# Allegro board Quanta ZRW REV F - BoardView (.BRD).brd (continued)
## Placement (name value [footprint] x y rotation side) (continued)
D11  *rb500v-40  [DSM]  198.34 40.64 270 top
D12  sdmk0340l-7-f  [DSMV]  200.24 40.64 270 top
D14  *rb500v-40  [DSM]  203.92 40.64 270 top
D15  *rb500v-40  [DSM]  44.16 39.75 180 top
D16  rb500v-40  [DSM]  44.16 37.71 180 top
D17  *rb500v-40  [DSM]  198.44 33.52 270 top
D18  rb500v-40  [DSM]  200.22 33.52 270 top
D19  *rb500v-40  [DSM]  201.99 33.52 270 top
D20  *rb500v-40  [DSM]  203.77 33.52 270 top
D21  az5725-01f  [D-SOD523-1_2X0_8-0_65H]  14.06 21.1 90 top
D22  az5725-01f  [D-SOD523-1_2X0_8-0_65H]  18.76 10.41 0 top
D23  *vport_6  [RC0603]  66.13 8.76 90 top
D24  *5.5v/25v/410p_4  [CC0402]  67.4 7.49 90 top
D25  *5.5v/25v/410p_4  [CC0402]  68.54 7.49 90 top
D26  *5.5v/25v/410p_4  [CC0402]  59.27 7.36 90 top
D27  *5.5v/25v/410p_4  [CC0402]  60.41 7.36 90 top
D28  *vport_6  [RC0603]  63.33 6.73 0 top
D30  rb501v-40  [DSM]  17.11 67.05 180 bottom
D31  rb501v-40  [DSM]  17.11 65.27 180 bottom
D33  *az5125-01h.r7g  [D-SOD523-1_2X0_8-0_65H]  14.06 20.95 90 bottom
D34  *vport_6  [RC0603]  144.74 15.87 90 bottom
D35  gs@rb500v-40  [DSM]  208.24 54.43 90 top
HOLE1  *h-tc315bc354d217p2  [H-TC315BC354D217P2]  229.4 191.7 0 top
HOLE2  *h-tc315bc354d134p2  [H-TC315BC354D134P2]  121.89 177.9 0 top
HOLE3  *h-tc256ic201bc236d161p2  [H-TC256IC201BC236D161P2]  136.52 146.63 0 top
HOLE4  *o-zrta-4  [O-ZRTA-4]  224.89 131.4 0 top
HOLE5  *h-zrw-1  [H-ZRW-1]  10.99 119.9 0 top
HOLE6  *h-tc256ic201bc236d161p2  [H-TC256IC201BC236D161P2]  110.53 101.64 0 top
HOLE7  *h-tc256ic201bc236d161p2  [H-TC256IC201BC236D161P2]  162.5 101.63 0 top
HOLE8  *h-o112x120d112x120n  [H-O112X120D112X120N]  5.29 99.4 90 top
HOLE9  *o-zrta-2  [O-ZRTA-2]  71.89 84.9 0 top
HOLE10  *h-o152x93d152x93n  [H-O152X93D152X93N]  231.15 84.9 0 top
HOLE11  *o-zrta-3  [O-ZRTA-3]  225.4 84.9 0 top
HOLE12  *h-tc315bc354d134p2  [H-TC315BC354D134P2]  17.27 58.62 0 top
HOLE13  *o-zrz-7  [O-ZRZ-7]  186.65 36.2 0 top
HOLE14  *h-o138x114d138x114n  [H-O138X114D138X114N]  217.89 26.3 0 top
HOLE15  *o-zrz-8  [O-ZRZ-8]  185.14 15.65 0 top
HOLE16  *h-c118d118  [H-C118D118]  12.79 5.9 0 top
HOLE17  *o-zrta-5  [O-ZRTA-5]  6.39 5.1 0 top
HOLE18  *h-tc315bc354d134p2  [H-TC315BC354D134P2]  217.89 5.1 0 top
HOLE19  *h-tc315bc354d134p2  [H-TC315BC354D134P2]  74.57 5.1 0 top
HOLE20  ev@mbzrq001010  [H-C236IC180D140P2]  161.21 178.33 180 bottom
HOLE21  ev@mbzrq001010  [H-C236D140P2]  203.42 136.13 180 bottom
HOLE22  h-c236d142p2  [H-C236D142P2]  213.09 99.47 180 bottom
HOLE23  *h-c256d134p2  [H-C256D134P2]  11.34 99.4 0 top
J1  *jump  [JOPEN25X30_S]  81.88 77.72 180 bottom
JDIM1  ddr3-dimm1_h=4.0_rvs  [DDR-DDRRK-20401-TP5B-204P-RUV]  132.89 64.35 180 bottom
JDIM2  ddr3-dimm1_h=4.0_std  [DDR-DDRSK-20401-TP4B-204P-SMT]  132.89 51.15 0 bottom
JP16  gt3@0.001/f_3720  [RC3720-SMT]  54.83 74.04 0 bottom
L1  ev@blm15px330sn1dev_4  [RC0402]  168.62 164.08 270 top
L2  ev@blm15px330sn1d_4  [RC0402]  185.7 142.89 0 top
L3  ev@hcb1005kf-181t15(180,1500ma)  [RC0402]  183.35 142.24 270 top
L4  80ohm@100mhz  [RC0402]  27.14 112.64 0 top
L5  blm18bb470_6  [RC0603]  13.42 108.78 0 top
L6  blm18bb470_6  [RC0603]  13.42 107.52 0 top
L7  blm18bb470_6  [RC0603]  13.42 105.49 0 top
L11  blm15ag121sn1d(120,500ma)_4  [RC0402]  197.4 37.79 0 top
L12  blm15ag121sn1d(120,500ma)_4  [RC0402]  197.4 36.78 0 top
L13  pby160808t-600y-n(60,3a)  [RC0603]  46.06 36.06 0 top
L16  hcb2012kf220t60/6a/22ohm_8  [RC0805]  45.38 31.75 0 top
L18  hcb1608kf-121t30_3a  [RC0603]  40.45 27.43 90 top
L19  *short_6  [SHORT0603]  204.94 24.76 0 top
L20  80ohm@100mhz  [RC0402]  24.85 111.63 90 bottom
L21  80ohm@100mhz  [RC0402]  17.18 106.52 270 bottom
L22  blm15ag121sn1d(120,500ma)_4  [RC0402]  207.73 49.14 270 bottom
LED1  led_amber/blue  [LEDLTST-S326KGJRKT-3P-SMT]  58.92 4.39 0 bottom
LED2  led_amber/blue  [LEDLTST-S326KGJRKT-3P-SMT]  66.89 4.39 0 bottom
MR1  ah9249ntr-g1  [SOT23_123-2_8-1_9]  62.9 2.92 270 top
NOREF  -  [unnamed]  221.22 19.78 0 top
NOREF#2  -  [unnamed]  20.94 118.99 0 top
NOREF#3  -  [#2]  112.1 -37.6 0 top
NOREF#4  -  [#2]  108.55 17.52 0 top
NOREF#5  -  [#2]  64.66 62.94 0 top
NOREF#6  -  [#2]  61.3 -79.76 0 top
NOREF#7  -  [unnamed]  229.83 199.26 0 top
NOREF#8  -  [#2]  119.21 17.78 180 bottom
NOREF#9  -  [#2]  89.57 51.28 180 bottom
NOREF#10  -  [unnamed]  16.7 117.29 180 bottom
NOREF#11  -  [unnamed]  228.05 199.39 180 bottom
NOREF#12  -  [unnamed]  221.75 28.62 180 bottom
PC1  *0.01u/50v_4  [CC0402]  179.57 200.53 0 top
PC2  0.1u/50v_6  [CC0603]  204.43 199.64 180 top
PC3  100p/50v_4  [CC0402]  210.02 199.13 180 top
PC4  *680p/50v_6  [CC0603]  194.4 198.5 180 top
PC5  0.1u/50v_6  [CC0603]  204.3 198.12 0 top
PC6  100p/50v_4  [CC0402]  210.02 197.99 180 top
PC7  *100p/50v_4  [CC0402]  210.02 196.97 180 top
PC8  *47p/50v_4  [CC0402]  158.58 195.96 90 top
PC9  *47p/50v_4  [CC0402]  160.62 195.96 90 top
PC10  0.01u/50v_4  [CC0402]  150.46 192.53 270 top
PC11  *0.01u/50v_4  [CC0402]  151.47 192.53 270 top
PC12  *0.01u/50v_4  [CC0402]  150.96 190.88 0 top
PC13  0.1u/50v_6  [CC0603]  214.97 190.11 180 top
PC14  0.1u/25v_4  [CC0402]  150.46 189.23 270 top
PC15  1000p/50v_4  [CC0402]  151.47 189.23 270 top
PC16  330p/25v_4  [CC0402]  152.49 189.23 270 top
PC17  0.022u/25v_4  [CC0402]  146.39 187.19 270 top
PC18  0.022u/25v_4  [CC0402]  147.41 187.19 270 top
PC19  *2200p/50v_4  [CC0402]  148.42 187.19 270 top
PC20  33nf/25v_4  [CC0402]  149.44 187.19 90 top
PC21  33p/50v_4  [CC0402]  153.5 187.19 90 top
PC22  330p/50v_4  [CC0402]  154.52 187.19 270 top
PC23  330p/50v_4  [CC0402]  144.49 184.27 0 top
PC24  33p/50v_4  [CC0402]  144.49 183.26 180 top
PC25  *0.01u/50v_4  [CC0402]  139.41 182.37 180 top
PC26  1000p/50v_4  [CC0402]  142.46 182.24 0 top
PC27  *0.01u/50v_4  [CC0402]  140.93 181.73 90 top
PC28  680p/50v_4  [CC0402]  142.46 181.22 0 top
PC29  0.01u/50v_4  [CC0402]  139.41 181.1 180 top
PC30  0.022u/25v_4  [CC0402]  144.49 180.21 0 top
PC31  0.1u/25v_4  [CC0402]  144.49 179.19 180 top
PC32  0.1u/25v_4  [CC0402]  155.16 179.07 180 top
PC33  0.1u/25v_4  [CC0402]  141.95 178.68 90 top
PC34  *2200p/50v_4  [CC0402]  144.49 178.18 180 top
PC35  0.1u/25v_4  [CC0402]  155.16 178.05 180 top
PC36  330p/50v_4  [CC0402]  147.54 176.53 90 top
PC37  33p/50v_4  [CC0402]  148.55 176.53 270 top
PC38  0.047u/10v_4  [CC0402]  151.6 176.53 90 top
PC39  0.01u/50v_4  [CC0402]  152.62 176.53 270 top
PC40  *2200p/50v_4  [CC0402]  153.63 176.53 270 top
PC41  *680p/50v_4  [CC0402]  149.57 174.49 90 top
PC42  1500p/50v_4  [CC0402]  150.58 174.49 90 top
PC43  0.1u/25v_4  [CC0402]  153.12 173.99 180 top
PC44  *0.01u/50v_4  [CC0402]  150.08 172.97 0 top
PC45  0.01u/50v_4  [CC0402]  149.44 171.45 270 top
PC46  *0.01u/50v_4  [CC0402]  150.71 171.45 270 top
PC47  10u/25v_8  [CC0805]  130.14 167.13 270 top
PC48  2200p/50v_6  [CC0603]  128.49 166.75 90 top
PC49  10u/25v_8  [CC0805]  139.41 165.73 270 top
PC50  2200p/50v_6  [CC0603]  137.76 165.35 90 top
PC51  2200p/50v_6  [CC0603]  148.68 165.35 90 top
PC52  10u/25v_8  [CC0805]  150.33 165.35 270 top
PC53  2200p/50v_6  [CC0603]  159.47 165.35 90 top
PC54  10u/25v_8  [CC0805]  161.12 165.35 270 top
PC55  1000p/50v_4  [CC0402]  126.12 164.17 270 top
PC56  1000p/50v_4  [CC0402]  135.17 163 270 top
PC57  1000p/50v_4  [CC0402]  155.92 162.81 270 top
PC58  1000p/50v_4  [CC0402]  144.61 162.68 270 top
PC59  330u/2v_7343  [CC7343]  146.65 154.3 0 top
PC60  ev@330u/2v_7343  [CC7343]  189.19 129.92 270 top
PC62  *680p/50v_6  [CC0603]  80.48 121.28 270 top
PC64  ev@1000p/50v_6  [CC0603]  191.73 118.11 90 top
PC65  *680p/50v_6  [CC0603]  215.99 117.09 90 top
PC66  ev@1000p/50v_6  [CC0603]  201.88 117.04 90 top
PC67  ev@2200p/50v_4  [CC0402]  203.03 114.17 0 top
PC68  ev@10u/25v_8  [CC0805]  190.11 113.15 180 top
PC69  ev@10u/25v_8  [CC0805]  202.91 112.64 0 top
PC72  ev@0.1u/50v_6  [CC0603]  203.03 110.99 180 top
PC73  ev@0.1u/50v_6  [CC0603]  196.3 110.23 90 top
PC79  ev@1u/10v_4  [CC0402]  201.97 106.93 0 top
PC81  ev@0.22u/25v_6  [CC0603]  206.69 105.86 0 top
PC82  ev@0.22u/25v_6  [CC0603]  198.03 105.84 180 top
PC89  ev@4700p/25v_4  [CC0402]  206.44 102.33 180 top
PC92  *e@0.01u/50v_4  [CC0402]  201.92 99.36 270 top
PC93  ev@1u/10v_4  [CC0402]  203.03 99.34 270 top
PC94  *ev@22p/50v_4  [CC0402]  207.61 98.75 90 top
PC95  *ev@1u/10v_4  [CC0402]  194.3 97.81 90 top
PC96  ev@2700p/50v_4  [CC0402]  201.43 97.66 180 top
PC99  gt3@10u/25v_8  [CC0805]  53.68 83.05 270 top
PC100  gt3@2200p/50v_4  [CC0402]  55.21 82.93 90 top
PC101  *2.2n/50v_4  [CC0402]  202.27 75.05 90 top
PC102  0.1u/50v_6  [CC0603]  74.26 73.78 0 top
PC103  2200p/50v_4  [CC0402]  46.32 70.99 270 top
PC104  0.1u/50v_6  [CC0603]  71.59 63.88 180 top
PC109  *ev@1u/10v_4  [CC0402]  81.85 9.55 270 top
PC113  *ev@2.2n/50v_4  [CC0402]  79.62 15.21 90 top
PC115  1u/25v_6  [CC0603]  203.16 200.78 180 bottom
PC116  0.47u/25v_6  [CC0603]  201 199.34 180 bottom
PC117  2200p/50v_6  [CC0603]  196.05 199.26 270 bottom
PC118  10u/25v_8  [CC0805]  197.7 199.23 90 bottom
PC119  47n/50v_6  [CC0603]  200.19 198.12 0 bottom
PC120  10u/25v_8  [CC0805]  178.02 195.7 90 bottom
PC121  2200p/50v_6  [CC0603]  179.67 195.7 270 bottom
PC122  2.2u/10v_6  [CC0603]  200.37 195.45 0 bottom
PC123  0.01u/50v_4  [CC0402]  203.8 192.27 180 bottom
PC124  2200p/50v_6  [CC0603]  217.77 192.15 180 bottom
PC125  *100p/50v_4  [CC0402]  167.29 191.66 270 bottom
PC126  0.1u/50v_6  [CC0603]  166.02 191.41 90 bottom
PC127  10u/25v_8  [CC0805]  170.01 191.13 180 bottom
PC128  0.1u/50v_6  [CC0603]  217.77 190.88 180 bottom
PC129  8200p/50v_4  [CC0402]  153.5 189.23 270 bottom
PC130  0.1u/25v_4  [CC0402]  204.18 188.46 180 bottom
PC131  0.1u/25v_4  [CC0402]  206.21 188.46 0 bottom
PC132  0.1u/25v_4  [CC0402]  208.24 188.46 0 bottom
PC133  1n/50v_4  [CC0402]  212.43 188.08 90 bottom
PC134  0.15u/10v_4  [CC0402]  149.44 187.19 270 bottom
PC135  3300p/50v_4  [CC0402]  142.46 183.26 0 bottom
PC136  47n/50v_6  [CC0603]  214.72 181.86 0 bottom
PC138  33u/25v_6x4.5  [ECAP6_3X6_1-7_2]  137.86 178.94 270 bottom
PC139  8200p/50v_4  [CC0402]  147.54 176.27 90 bottom
PC140  2200p/50v_6  [CC0603]  222.47 171.32 270 bottom
PC141  0.1u/50v_6  [CC0603]  223.74 171.32 90 bottom
PC142  0.1u/25v_6  [CC0603]  127.98 170.05 0 bottom
PC143  0.1u/25v_6  [CC0603]  136.61 169.54 90 bottom
PC144  0.1u/25v_6  [CC0603]  147.54 169.41 90 bottom
PC145  0.1u/25v_6  [CC0603]  158.2 169.41 90 bottom
PC146  4.7u/10v_6  [CC0603]  122.77 167.89 270 bottom
PC147  4.7u/10v_6  [CC0603]  132.04 167.51 270 bottom
PC148  10u/25v_8  [CC0805]  130.14 167.13 270 bottom
PC149  4.7u/10v_6  [CC0603]  142.96 166.87 270 bottom
PC150  0.1u/50v_6  [CC0603]  128.49 166.75 90 bottom
PC151  4.7u/10v_6  [CC0603]  153.89 166.75 270 bottom
PC152  10u/25v_8  [CC0805]  139.41 165.73 270 bottom
PC153  0.1u/50v_6  [CC0603]  137.76 165.35 90 bottom
PC154  0.1u/50v_6  [CC0603]  148.68 165.35 90 bottom
PC155  10u/25v_8  [CC0805]  150.33 165.35 270 bottom
PC156  0.1u/50v_6  [CC0603]  159.47 165.35 90 bottom
PC157  10u/25v_8  [CC0805]  161.12 165.35 270 bottom
PC158  330u/2v_7343  [CC7343]  121.5 158.44 90 bottom
PC159  0.1u/16v_4  [CC0402]  131.53 156.08 270 bottom
PC160  0.1u/16v_4  [CC0402]  139.66 153.03 180 bottom
PC161  0.1u/16v_4  [CC0402]  141.69 153.03 0 bottom
PC162  330u/2v_7343  [CC7343]  151.17 152.5 270 bottom
PC163  330u/2v_7343  [CC7343]  122.52 151.33 180 bottom
PC164  22u/6.3v_8  [CC0805]  141.95 151.25 0 bottom
PC165  22u/6.3v_8  [CC0805]  157.57 151.25 180 bottom
PC166  22u/6.3v_8  [CC0805]  129.37 149.35 90 bottom
PC167  22u/6.3v_8  [CC0805]  131.41 149.35 90 bottom
PC168  22u/6.3v_8  [CC0805]  141.95 149.22 0 bottom
PC169  22u/6.3v_8  [CC0805]  157.57 149.22 180 bottom
PC170  22u/6.3v_8  [CC0805]  120.23 147.95 0 bottom
PC171  0.1u/16v_4  [CC0402]  157.31 147.06 90 bottom
PC172  22u/6.3v_8  [CC0805]  120.23 145.92 0 bottom
PC173  4.7u/6.3v_6  [CC0603]  104.23 140.33 180 bottom
PC174  0.47uf/4v_4  [CC0402]  104.86 134.49 180 bottom
PC175  0.1u/16v_4  [CC0402]  99.28 133.85 180 bottom
PC176  ev@0.1u/50v_6  [CC0603]  217.64 133.73 0 bottom
PC177  ev@0.1u/16v_4  [CC0402]  198.21 133.47 270 bottom
PC178  ev@0.1u/16v_4  [CC0402]  199.22 133.47 270 bottom
PC179  ev@22u/6.3v_8  [CC0805]  210.15 133.35 180 bottom
PC180  ev@10u/6.3v_8  [CC0805]  188.81 133.14 270 bottom
PC181  ev@10u/6.3v_8  [CC0805]  195.01 133.14 270 bottom
PC182  ev@22u/6.3v_8  [CC0805]  217.64 131.95 0 bottom
PC183  *10u/6.3v_6  [CC0603]  99.15 131.31 0 bottom
PC184  10u/6.3v_6  [CC0603]  99.15 130.04 0 bottom
PC185  ev@330u/2.5v_6x4.2  [ECAP6_3X6_1-7_2]  184.11 129.89 90 bottom
PC186  ev@22u/6.3v_8  [CC0805]  209.77 128.14 270 bottom
PC187  ev@22u/6.3v_8  [CC0805]  218.78 127.5 270 bottom
PC189  ev@330u/2v_7343  [CC7343]  206.34 127.12 270 bottom
PC191  ev@0.1u/50v_6  [CC0603]  218.4 124.07 270 bottom
PC193  ev@0.1u/16v_4  [CC0402]  210.91 120.65 180 bottom
PC194  1u/10v_4  [CC0402]  80.15 114.3 0 bottom
PC195  ev@1u/6.3v_4  [CC0402]  219.04 119.5 0 bottom
PC196  0.1u/50v_6  [CC0603]  80.4 113.15 0 bottom
PC199  *ev@0.1u/16v_4  [CC0402]  219.04 116.45 180 bottom
PC200  ev@2200p/50v_6  [CC0603]  215.48 116.07 180 bottom
PC202  10u/25v_8  [CC0805]  74.71 119.48 270 bottom
PC203  2200p/50v_6  [CC0603]  76.49 119.48 90 bottom
PC204  ev@0.1u/50v_6  [CC0603]  215.48 114.8 180 bottom
PC205  ev@10u/25v_8  [CC0805]  190.33 113.56 180 bottom
PC206  ev@0.1u/50v_6  [CC0603]  215.48 113.53 180 bottom
PC207  ev@10u/25v_8  [CC0805]  202.91 112.64 0 bottom
PC208  ev@2200p/50v_4  [CC0402]  190.08 112.01 180 bottom
PC209  ev@10u/25v_8  [CC0805]  216.5 111.88 0 bottom
PC210  ev@33u/25v_6x4.5  [ECAP6_3X6_1-7_2]  222.59 110.36 90 bottom
PC211  ev@10u/25v_8  [CC0805]  216.5 109.85 0 bottom
PC212  330u/2.5v_6x4.2  [ECAP6_3X6_1-7_2]  88.73 116.45 0 bottom
PC213  0.1u/50v_6  [CC0603]  96.23 121.79 0 bottom
PC214  ev@22p/50v_4  [CC0402]  206.46 102.36 180 bottom
PC219  *ev@0.01u/50v_4  [CC0402]  201.43 97.63 0 bottom
PC222  gt3@22uf/6.3v_6  [CC0603]  61.56 92.07 0 bottom
PC223  gt3@22uf/6.3v_6  [CC0603]  65.37 92.07 180 bottom
PC225  gt3@22uf/6.3v_6  [CC0603]  61.56 90.8 0 bottom
PC226  gt3@0.1u/16v_4  [CC0402]  65.11 90.8 180 bottom
PC228  gt3@10u/25v_8  [CC0805]  53.68 83.05 270 bottom
PC229  gt3@0.1u/25v_4  [CC0402]  55.21 82.93 270 bottom
PC230  gt3@1u/10v_4  [CC0402]  57.62 80.01 180 bottom
PC231  gt3@0.1u/50v_6  [CC0603]  60.44 79.24 270 bottom
PC232  ev@22u/6.3v_6  [CC0603]  191.99 77.85 180 bottom
PC233  ev@0.1u/16v_4  [CC0402]  192.24 76.58 0 bottom
PC234  10u/6.3v_6  [CC0603]  180.07 72.03 180 bottom
PC235  10u/6.3v_6  [CC0603]  177.76 71.37 90 bottom
PC236  10u/6.3v_6  [CC0603]  180.07 70.81 180 bottom
PC237  0.22u/10v_4  [CC0402]  183.35 70.61 180 bottom
PC238  0.1u/16v_4  [CC0402]  183.35 69.52 180 bottom
PC239  0.01u/50v_4  [CC0402]  182.84 66.8 90 bottom
PC240  *ev@0.1u/16v_4  [CC0402]  193.26 64.77 270 bottom
PC241  *ev@2200p/50v_4  [CC0402]  188.3 64 0 bottom
PC242  1u/10v_4  [CC0402]  180.71 63.65 270 bottom
PC243  0.1u/50v_6  [CC0603]  179.46 63.37 270 bottom
PC244  *ev@22p/50v_4  [CC0402]  193.76 61.21 180 bottom
PC245  10u/25v_8  [CC0805]  179.03 61.06 180 bottom
PC246  ev@0.01u/50v_4  [CC0402]  187.79 60.57 0 bottom
PC247  *ev@68p/50v_4  [CC0402]  193.76 60.07 0 bottom
PC248  2200p/50v_4  [CC0402]  178.52 59.53 0 bottom
PC249  ev@10u/6.3v_6  [CC0603]  187.92 59.3 0 bottom
PC250  *680p/50v_6  [CC0603]  184.47 59.03 270 bottom
PC252  ev@1u/6.3v_4  [CC0402]  193.76 58.92 0 bottom
PC259  10u/6.3v_6  [CC0603]  69.58 22.14 270 bottom
PC261  *10u/6.3v_6  [CC0603]  70.85 22.16 270 bottom
PC265  0.1u/16v_4  [CC0402]  72.07 21.89 90 bottom
PC268  0.1u/50v_6  [CC0603]  177.76 48.38 90 bottom
PC271  0.47uf/4v_4  [CC0402]  75.4 18.16 270 bottom
PC275  330u/2.5v_6x4.2  [ECAP6_3X6_1-7_2]  175.6 43.43 90 bottom
PC278  4.7u/6.3v_6  [CC0603]  84.04 21.89 180 bottom
PC282  *2.2n/50v_4  [CC0402]  53.68 33.37 180 bottom
PC6097  0.1u/50v_6  [CC0603]  58.5 55.45 270 top
PC6098  4.7u/6.3v_6  [CC0603]  65.85 55.4 180 top
PC6099  0.1u/50v_6  [CC0603]  60.85 52.95 180 top
PC6100  0.1u/25v_4  [CC0402]  66.21 52.29 90 top
PC6209  0.1u/50v_6  [CC0603]  58.39 60.34 180 bottom
PC6211  0.1u/50v_6  [CC0603]  60.91 55.56 0 bottom
PC6212  33u/25v_6x4.5  [ECAP6_3X6_1-7_2]  56.04 54.51 270 bottom
PC6213  0.1u/50v_6  [CC0603]  70.67 53.39 180 bottom
PC6214  2200p/50v_4  [CC0402]  75.18 53.35 0 bottom
PC6215  0.1u/50v_6  [CC0603]  60.93 53.02 180 bottom
PC6216  10u/25v_8  [CC0805]  75.31 51.57 0 bottom
PC6218  2200p/50v_4  [CC0402]  59.92 50 180 bottom
PC6219  10u/6.3v_6  [CC0603]  66.15 49.2 270 bottom
PC6220  10u/25v_8  [CC0805]  60.05 48.47 180 bottom
PC6221  *680p/50v_6  [CC0603]  67.34 47.06 270 bottom
PC6222  *680p/50v_6  [CC0603]  69.72 45.67 270 bottom
PC6224  220u/6.3v_6x4.2  [ECAP6_3X6_1-7_2]  82.39 41.43 270 bottom
PC6225  0.1u/50v_6  [CC0603]  71.29 39.06 90 bottom
PC6226  0.1u/50v_6  [CC0603]  70.02 39.06 90 bottom
PC6227  220u/6.3v_6x4.2  [ECAP6_3X6_1-7_2]  58.71 37.28 270 bottom
PC6228  1000p/50v_4  [CC0402]  158.71 183.38 270 top
PC6229  33u/25v_6x4.5  [ECAP6_3X6_1-7_2]  130.92 178.91 270 bottom
PC6230  22u/6.3v_6  [CC0603]  111.59 143.51 0 bottom
PC6231  *22u/6.3v_6  [CC0603]  100.04 122.04 90 bottom
PD1  pdz5.6b  [DSM]  158.2 199.64 90 top
PD2  pdz5.6b  [DSM]  160.36 199.64 90 top
PD3  p4smafj20a  [D-DO-214AC]  218.78 198.5 180 top
PD4  da2j10100l  [DSM]  80.23 69.46 0 top
PD8  sv1040  [D-TO277_213-6_1X4_3]  221.7 187.19 90 bottom
PD6004  1ps302  [UMT_213-3-1_3]  61.78 55.39 0 top
PD6008  1ps302  [UMT_213-3-1_3]  61.01 57.92 90 bottom
PJ1  50458-00801-v01  [50458-00801-V02-8P-L]  161.24 198.88 0 bottom
PJ2  power conn  [20288-04XX-4P-L]  217.89 194.4 180 bottom
PL1  6.8uh_7x7x3  [CHOKE-PCMC063T-3R3MN-SMT]  186.02 199.51 0 bottom
PL2  0.24uh_7x7x4  [CHOKE-PCMC063T-R82MN-4P-SMT]  127.42 158.75 270 bottom
PL3  0.24uh_7x7x4  [CHOKE-PCMC063T-R82MN-4P-SMT]  136.31 157.6 270 bottom
PL4  0.15uh_7x7x4  [CHOKE-PCMC063T-R82MN-4P-SMT]  145 157.48 270 bottom
PL5  0.47uh_7x7x3  [CHOKE-PCMC063T-R82MN-4P-SMT]  157.31 157.48 270 bottom
PL6  2.2uh/1.85a_2.5x2x1.2  [L3_2X2_5-1_55]  100.32 136.62 270 bottom
PL7  ev@0.24uh_7x7x3  [CHOKE-ETQP4LR36AFM]  191.86 127.63 90 bottom
PL8  ev@0.24uh_7x7x3  [CHOKE-ETQP4LR36AFM]  200.11 126.61 90 bottom
PL9  ev@3.3uh_7x7x3  [CHOKE-PCMC063T-3R3MN-SMT]  214.21 126.23 90 bottom
PL11  0.68uh_7x7x3  [CHOKE-PCMC063T-3R3MN-SMT]  87.59 124.07 0 bottom
PL13  gt3@0.68uh_7x7x3  [CHOKE-PCMC063T-3R3MN-SMT]  62.95 85.34 90 bottom
PL14  ev@1uh_7x7x3  [CHOKE-PCMC063T-3R3MN-SMT]  188.3 70.99 90 bottom
PL15  1uh_7x7x3  [CHOKE-PCMC063T-3R3MN-SMT]  181.95 49.27 270 bottom
PL16  2.2uh/1.85a_2.5x2x1.2  [L3_2X2_5-1_55]  74.79 21.38 180 bottom
PL6012  2.2uh_7x7x3  [CHOKE-PCMC063T-3R3MN-SMT]  75.43 41.11 270 bottom
PL6013  2.2uh_7x7x3  [CHOKE-PCMC063T-3R3MN-SMT]  65.7 37.98 90 bottom
PQ1  aon6414al  [SO-8FL-5P-OA]  173.57 198.6 0 top
PQ2  *ev@2n7002k  [SOT23_213-3_3-2]  196.91 97.33 180 top
PQ3  2n7002k  [SOT23_213-3_3-2]  46.32 74.16 90 top
PQ4  2n7002k  [SOT23_213-3_3-2]  50.13 74.16 90 top
PQ5  2n7002k  [SOT23_213-3_3-2]  53.94 74.16 90 top
PQ6  dtc144eu  [UMT_213-3-1_3]  198.72 72 270 top
PQ7  2n7002k  [SOT23_213-3_3-2]  195.39 71.88 270 top
PQ8  2n7002k  [SOT23_213-3_3-2]  202.04 71.88 270 top
PQ9  2n7002k  [SOT23_213-3_3-2]  75.27 70.35 0 top
PQ10  2n7002k  [SOT23_213-3_3-2]  53.94 70.23 90 top
PQ11  dtc144eu  [UMT_213-3-1_3]  57.26 69.97 90 top
PQ12  ao3409  [SOT23_213-3_3-2]  76.67 66.54 0 top
PQ13  dtc144eu  [UMT_213-3-1_3]  81.47 66.16 90 top
PQ14  2n7002k  [SOT23_213-3_3-2]  76.8 61.34 0 top
PQ15  ev@pdtc143tt  [SOT23_213-3_3-2]  80.99 12.57 270 top
PQ16  ev@2n7002k  [SOT23_213-3_3-2]  77.18 12.57 270 top
PQ17  ev@2n7002k  [SOT23_213-3_3-2]  73.37 12.57 270 top
PQ18  mdv1528q  [WDFN5-3_05X3_05-65]  84.19 26.62 180 bottom
PQ19  ev@ao3404  [SOT23_213-3_3-2]  76.95 17.04 180 top
PQ20  aon7410  [WDFN5-3_05X3_05-65]  193 201.04 180 bottom
PQ21  aon7410  [WDFN5-3_05X3_05-65]  193.13 196.57 0 bottom
PQ22  aon6414al  [SO-8FL-5P-OA]  216.12 187.45 270 bottom
PQ23  ao3404  [SOT23_213-3_3-2]  108.29 142.49 90 bottom
PQ24  ev@aon6752  [SO-8FL-5P-OA]  193.13 119.5 270 bottom
PQ25  ev@aon6414al  [SO-8FL-5P-OA]  187.03 118.87 90 bottom
PQ26  mdv1528q  [WDFN5-3_05X3_05-65]  98.13 118.74 0 bottom
PQ27  ev@aon6752  [SO-8FL-5P-OA]  199.78 118.56 270 bottom
PQ29  ev@aon6414al  [SO-8FL-5P-OA]  206.34 116.58 90 bottom
PQ30  aon6978  [POWER-5X6-1_27-7P]  79.97 118.74 270 bottom
PQ31  aon7752  [WDFN5-3_05X3_05-65]  181.55 56.79 90 bottom
PQ32  aon7410  [WDFN5-3_05X3_05-65]  176.92 56.61 270 bottom
PQ33  2n7002k  [SOT23_213-3_3-2]  62.9 32.13 270 bottom
PQ34  mdv1528q  [WDFN5-3_05X3_05-65]  79.45 32.78 90 bottom
PQ35  dtc144eu  [UMT_213-3-1_3]  57.72 30.68 270 bottom
PQ36  2n7002k  [SOT23_213-3_3-2]  69.75 29.38 0 bottom
PQ37  ao3404  [SOT23_213-3_3-2]  73.47 27.53 0 bottom
PQ38  mdv1528q  [WDFN5-3_05X3_05-65]  79.45 28.08 0 bottom
PQ39  2n7002k  [SOT23_213-3_3-2]  54.39 28.37 0 bottom
PQ40  *ev@2n7002k  [SOT23_213-3_3-2]  199.73 144.27 270 top
PQ6053  aon7752  [WDFN5-3_05X3_05-65]  73.74 48.3 180 bottom
PQ6054  aon7410  [WDFN5-3_05X3_05-65]  78.4 48.08 270 bottom
PQ6055  aon7752  [WDFN5-3_05X3_05-65]  64.3 45.14 90 bottom
PQ6056  aon7410  [WDFN5-3_05X3_05-65]  59.76 45.01 270 bottom
PQ6057  *2n7002k  [SOT23_213-3_3-2]  89.93 30.37 0 top
PQ6058  *2n7002k  [SOT23_213-3_3-2]  89.93 34.18 0 top
PQ6059  *2n7002k  [SOT23_213-3_3-2]  174.59 45.54 270 top
PQ6060  *2n7002k  [SOT23_213-3_3-2]  169.76 44.29 0 top
PR1  100k/f_4  [RC0402]  206.87 199.51 90 top
PR2  *4.7_6  [RC0603]  191.73 198.5 180 top
PR3  133k/f_4  [RC0402]  207.38 197.48 270 top
PR4  100k/f_4  [RC0402]  208.39 197.48 90 top
PR5  20_1206  [RC1206]  200.62 196.8 90 top
PR6  100_4  [RC0402]  157.57 195.96 270 top
PR7  100_4  [RC0402]  159.6 195.96 270 top
PR8  100_4  [RC0402]  162.27 195.96 270 top
PR9  1m_4  [RC0402]  163.28 195.96 90 top
PR10  *0_4  [RC0402]  164.3 195.96 90 top
PR11  100k_4  [RC0402]  207.86 195.45 180 top
PR12  *short_4  [SHORT0402]  210.15 194.81 180 top
PR13  *0_4  [RC0402]  210.15 193.67 0 top
PR14  316k/f_4  [RC0402]  206.84 193.54 180 top
PR15  100k/f_4  [RC0402]  205.07 193.42 90 top
PR16  10k_4  [RC0402]  210.15 192.53 180 top
PR17  1/f_6  [RC0603]  148.65 192.58 0 top
PR18  *100k/f_4  [RC0402]  144.74 189.61 90 top
PR19  100k/f_6  [RC0603]  146.01 189.61 270 top
PR20  3.65k/f_6  [RC0603]  147.28 189.61 270 top
PR21  *1k/f_4  [RC0402]  148.93 188.72 0 top
PR22  11k/f_4  [RC0402]  150.46 187.19 90 top
PR23  2k/f_4  [RC0402]  151.47 187.19 270 top
PR24  1k/f_4  [RC0402]  152.49 187.19 270 top
PR25  *short_4  [SHORT0402]  155.54 187.19 270 top
PR26  *short_4  [SHORT0402]  142.43 185.19 180 top
PR27  *short_4  [SHORT0402]  144.49 185.29 180 top
PR28  *short_4  [SHORT0402]  155.16 185.16 0 top
PR29  *short_4  [SHORT0402]  142.46 184.02 180 top
PR30  *short_4  [SHORT0402]  155.16 184.15 0 top
PR31  *10_4  [RC0402]  139.41 183.38 180 top
PR32  *short_4  [SHORT0402]  155.16 183.13 0 top
PR33  *short_4  [SHORT0402]  137.88 182.75 90 top
PR34  499/f_4  [RC0402]  144.49 182.24 0 top
PR35  49.9/f_4  [RC0402]  155.16 182.11 0 top
PR36  2k/f_4  [RC0402]  144.49 181.22 0 top
PR38  *short_4  [SHORT0402]  137.88 180.72 270 top
PR39  *10_4  [RC0402]  139.41 180.08 180 top
PR40  10_4  [RC0402]  155.16 180.72 180 top
PR41  *1k/f_4  [RC0402]  142.96 178.68 270 top
PR42  *short_4  [SHORT0402]  145.5 176.53 90 top
PR43  *short_4  [SHORT0402]  146.52 176.53 90 top
PR44  *2k/f_4  [RC0402]  149.57 176.53 90 top
PR45  499/f_4  [RC0402]  150.58 176.53 90 top
PR46  *short_4  [SHORT0402]  154.65 176.53 90 top
PR47  *short_4  [SHORT0402]  155.66 176.53 90 top
PR48  *1k/f_4  [RC0402]  153.12 175 0 top
PR49  *10_4  [RC0402]  148.42 171.45 270 top
PR50  *short_4  [SHORT0402]  151.73 171.45 270 top
PR51  *10_4  [RC0402]  153.25 170.94 180 top
PR52  *short_4  [SHORT0402]  153.25 169.92 180 top
PR53  *short_6  [SHORT0603]  122.77 167.89 90 top
PR54  *short_6  [SHORT0603]  132.04 167.51 90 top
PR55  *short_6  [SHORT0603]  142.96 166.87 90 top
PR56  *short_6  [SHORT0603]  153.96 166.68 270 top
PR57  2.2/f_6  [RC0603]  126.88 162.52 0 top
PR58  2.2/f_6  [RC0603]  135.93 161.34 0 top
PR59  2.2/f_6  [RC0603]  156.68 161.16 0 top
PR60  2.2/f_6  [RC0603]  145.38 161.03 0 top
PR61  *shortev@0_4  [SHORT0402]  187.31 136.19 90 top
PR62  *shortev@0_4  [SHORT0402]  188.48 136.19 90 top
PR63  *ev@100_4  [RC0402]  190.08 135.76 0 top
PR64  *ev@100_4  [RC0402]  186.27 135.4 270 top
PR65  ev@2.2/f_6  [RC0603]  191.73 121.03 90 top
PR66  10k/f_4  [RC0402]  73.93 114.3 180 top
PR67  ev@2.2/f_6  [RC0603]  201.88 120.09 90 top
PR68  *4.7_6  [RC0603]  215.99 119.76 90 top
PR69  *shortev@0_6  [SHORT0603]  219.42 119.5 90 top
PR71  470k/f_4  [RC0402]  73.93 113.03 0 top
PR72  *100k/f_4  [RC0402]  73.93 112.01 0 top
PR73  *shortev@0_4  [SHORT0402]  219.04 117.47 0 top
PR74  93.1k/f_4  [RC0402]  73.93 110.99 0 top
PR75  *ev@499k/f_4  [RC0402]  219.04 116.45 180 top
PR76  *4.7_6  [RC0603]  81.24 119.25 0 top
PR99  *shortev@0_6  [SHORT0603]  204.48 107.18 0 top
PR107  ev@2.2/f_6  [RC0603]  206.69 104.59 0 top
PR108  ev@2.2/f_6  [RC0603]  198.01 104.54 180 top
PR110  *shortev@0_4  [SHORT0402]  206.46 103.48 0 top
PR111  *ev@0_4  [RC0402]  197.8 103.3 180 top
PR116  *shortev@0_4  [SHORT0402]  197.8 102.08 0 top
PR120  *ev@0_4  [RC0402]  196.13 101.52 270 top
PR122  ev@16k/f_6  [RC0603]  206.69 101.24 180 top
PR123  *shortev@0_4  [SHORT0402]  197.8 101.06 0 top
PR124  *ev@10k_4  [RC0402]  194.98 100.38 90 top
PR125  *ev@10k_4  [RC0402]  196.63 99.84 0 top
PR126  ev@20k/f_4  [RC0402]  200.85 99.36 90 top
PR127  ev@20k/f_4  [RC0402]  204.18 99.34 90 top
PR128  *shortev@0_4  [SHORT0402]  205.37 98.75 270 top
PR129  *shortev@0_4  [SHORT0402]  206.46 98.75 270 top
PR130  *ev@5.1k/f_4  [RC0402]  199.61 98.55 270 top
PR131  ev@2k/f_4  [RC0402]  201.51 96.64 0 top
PR132  ev@18.2k/f_4  [RC0402]  199.61 96.52 90 top
PR134  *shortev@0_4  [SHORT0402]  198.29 95.6 270 top
PR135  *100k/f_4  [RC0402]  56.86 86.61 90 top
PR136  gt3@0_4  [RC0402]  57.87 86.61 90 top
PR137  22_8  [RC0805]  50.13 77.97 90 top
PR138  22_8  [RC0805]  53.94 77.97 90 top
PR139  22_8  [RC0805]  195.41 75.69 90 top
PR140  1m_6  [RC0603]  198.21 75.31 270 top
PR141  1m_6  [RC0603]  199.61 75.31 90 top
PR142  *1m_6  [RC0603]  201 75.31 90 top
PR143  1m_6  [RC0603]  203.54 75.31 90 top
PR144  200k/f_4  [RC0402]  70.57 75.05 0 top
PR145  200k/f_4  [RC0402]  69.43 73.78 0 top
PR146  1.47k/f_4  [RC0402]  71.46 73.78 180 top
PR147  *100k/f_6  [RC0603]  57.24 72.64 0 top
PR148  1m_4  [RC0402]  47.46 70.99 270 top
PR149  *short_6  [SHORT0603]  181.95 69.34 180 top
PR150  1m_4  [RC0402]  56.1 67.05 90 top
PR151  1m_4  [RC0402]  57.24 67.05 270 top
PR152  1m_6  [RC0603]  79.34 66.42 90 top
PR153  220_8  [RC0805]  53.81 66.29 270 top
PR154  *short_6  [SHORT0603]  73.88 66.04 90 top
PR155  200k_6  [RC0603]  74.64 63.88 180 top
PR157  ev@1m_4  [RC0402]  82.13 15.77 270 top
PR158  ev@100k_4  [RC0402]  80.71 9.55 90 top
PR159  ev@1m_4  [RC0402]  80.99 15.77 90 top
PR160  *shortev@0_4  [SHORT0402]  79.57 9.55 90 top
PR161  ev@1m_4  [RC0402]  78.47 15.21 90 top
PR164  ev@22_8  [RC0805]  71.59 15.82 0 top
PR165  4.02k/f_4  [RC0402]  206.21 200.45 90 bottom
PR166  4.02k/f_4  [RC0402]  205.07 200.4 90 bottom
PR167  *short_4  [SHORT0402]  207.48 200.4 270 bottom
PR168  866k/f_4  [RC0402]  208.5 200.4 90 bottom
PR169  0.01/f_0612  [RC3216]  178.85 199.89 90 bottom
PR170  *short_4  [SHORT0402]  210.15 199.39 180 bottom
PR171  *short_4  [SHORT0402]  210.15 198.24 180 bottom
PR172  *short_4  [SHORT0402]  210.15 197.1 180 bottom
PR173  *short_6  [SHORT0603]  200.24 196.64 180 bottom
PR174  *100k_4  [RC0402]  210.15 195.96 180 bottom
PR175  *short_4  [SHORT0402]  180.81 195.58 90 bottom
PR176  *short_4  [SHORT0402]  181.86 195.58 90 bottom
PR177  *short_4  [SHORT0402]  210.15 194.81 180 bottom
PR178  *short_4  [SHORT0402]  210.15 193.67 180 bottom
PR179  *10k_4  [RC0402]  210.15 192.53 180 bottom
PR180  *10_4  [RC0402]  150.96 192.15 0 bottom
PR181  *short_4  [SHORT0402]  150.96 190.88 0 bottom
PR182  1/f_6  [RC0603]  149.19 189.61 270 bottom
PR183  10/f_6  [RC0603]  204.69 190.37 270 bottom
PR184  10/f_6  [RC0603]  205.96 190.37 270 bottom
PR185  *short_6  [SHORT0603]  207.48 190.37 270 bottom
PR186  10/f_6  [RC0603]  209.38 190.37 270 bottom
PR187  *10_4  [RC0402]  151.98 189.73 0 bottom
PR188  *100k/f_4  [RC0402]  144.74 189.61 90 bottom
PR189  100k/f_6  [RC0603]  146.01 189.61 270 bottom
PR190  3.65k/f_6  [RC0603]  147.28 189.61 270 bottom
PR191  *short_4  [SHORT0402]  151.98 188.72 0 bottom
PR192  274/f_4  [RC0402]  148.42 187.19 90 bottom
PR193  2.61k/f_4  [RC0402]  150.46 187.19 270 bottom
PR194  1.91k/f_4  [RC0402]  152.49 187.19 270 bottom
PR195  1.69k/f_4  [RC0402]  153.5 187.19 270 bottom
PR196  *10k/f_4  [RC0402]  157.44 185.67 90 top
PR197  10k/f_4  [RC0402]  158.46 185.67 90 top
PR198  80.6k/f_4  [RC0402]  151.22 184.02 90 bottom
PR199  2.87k/f_4  [RC0402]  144.49 183.26 0 bottom
PR200  *10k/f_4  [RC0402]  155.16 183.13 180 bottom
PR201  1.37k/f_4  [RC0402]  144.49 182.24 0 bottom
PR202  90.9k/f_4  [RC0402]  147.66 182.24 180 bottom
PR203  78.7k/f_4  [RC0402]  151.85 181.1 0 bottom
PR204  1/f_6  [RC0603]  154.39 181.22 90 bottom
PR205  2.61k/f_4  [RC0402]  144.49 180.21 180 bottom
PR206  63.4k/f_4  [RC0402]  151.85 180.08 0 bottom
PR207  162k_4  [RC0402]  148.81 179.45 270 bottom
PR208  11k/f_4  [RC0402]  144.49 179.19 0 bottom
PR209  *short_4  [SHORT0402]  218.53 179.07 270 bottom
PR210  *short_4  [SHORT0402]  219.54 179.07 270 bottom
PR211  249/f_4  [RC0402]  144.49 178.18 0 bottom
PR212  *short_8  [SHORT0805]  155.16 177.92 270 bottom
PR213  0.01/f_0612  [RC3216]  222.47 177.67 180 bottom
PR214  1/f_6  [RC0603]  142.33 176.27 90 bottom
PR215  3.65k/f_6  [RC0603]  143.6 176.27 90 bottom
PR216  2k/f_4  [RC0402]  148.55 176.27 90 bottom
PR217  2.05k/f_4  [RC0402]  150.58 176.27 90 bottom
PR218  2.61k/f_4  [RC0402]  151.6 176.27 270 bottom
PR219  11k/f_4  [RC0402]  152.62 176.27 270 bottom
PR220  499/f_4  [RC0402]  153.63 176.27 90 bottom
PR221  1/f_6  [RC0603]  151.73 173.86 90 bottom
PR222  3.65k/f_6  [RC0603]  153 173.86 90 bottom
PR223  *short_6  [SHORT0603]  127.98 171.32 0 bottom
PR224  10k/f_4  [RC0402]  142.58 170.81 180 bottom
PR225  10k/f_4  [RC0402]  120.99 170.56 90 bottom
PR226  27.4k/f_4  [RC0402]  122.01 170.56 270 bottom
PR227  470k_4_4700ntc  [RC0402]  123.02 170.56 270 bottom
PR228  *short_4  [SHORT0402]  124.04 170.56 90 bottom
PR229  *short_4  [SHORT0402]  125.06 170.56 90 bottom
PR230  *short_6  [SHORT0603]  135.34 169.54 90 bottom
PR231  *short_6  [SHORT0603]  146.27 169.41 90 bottom
PR232  *short_6  [SHORT0603]  156.93 169.41 90 bottom
PR233  *short_4  [SHORT0402]  133.18 169.29 90 bottom
PR234  *short_4  [SHORT0402]  134.2 169.29 90 bottom
PR235  27.4k/f_4  [RC0402]  142.07 169.29 270 bottom
PR236  470k_4_4700ntc  [RC0402]  143.09 169.29 270 bottom
PR237  *short_4  [SHORT0402]  144.11 169.29 90 bottom
PR238  *short_4  [SHORT0402]  145.12 169.29 90 bottom
PR239  *short_4  [SHORT0402]  154.77 169.16 90 bottom
PR240  *short_4  [SHORT0402]  155.79 169.16 90 bottom
PR241  10k/f_4_3435ntc  [RC0402]  122.39 163.72 180 bottom
PR242  10k/f_4_3435ntc  [RC0402]  153.17 161.03 90 bottom
PR243  10k/f_4_3435ntc  [RC0402]  140.84 156.72 270 bottom
PR244  *short_4  [SHORT0402]  104.48 141.6 0 bottom
PR245  *short_4  [SHORT0402]  106.77 139.82 0 bottom
PR246  *short_4  [SHORT0402]  106.77 138.81 0 bottom
PR247  30k/f_4  [RC0402]  106.77 137.79 0 bottom
PR248  15k/f_4  [RC0402]  106.26 136.27 270 bottom
PR249  10k_4  [RC0402]  105.37 132.84 90 bottom
PR250  ev@1/f_6  [RC0603]  218.4 121.41 270 bottom
PR251  4.3k/f_4  [RC0402]  71.77 114.04 180 bottom
PR252  *shortev@0_4  [SHORT0402]  210.91 119.63 0 bottom
PR254  *short_4  [SHORT0402]  71.77 113.03 0 bottom
PR255  ev@100k/f_4  [RC0402]  210.91 118.61 180 bottom
PR256  ev@54.9k/f_4  [RC0402]  219.04 118.49 180 bottom
PR257  100k/f_4  [RC0402]  71.77 111.88 0 bottom
PR258  *short_6  [SHORT0603]  80.4 111.88 0 bottom
PR259  ev@82k/f_4  [RC0402]  219.04 117.47 180 bottom
PR260  *shortev@0_4  [SHORT0402]  211.92 117.6 180 bottom
PR262  10k/f_4_3435ntc  [RC0402]  109.94 112.14 90 bottom
PR266  ev@10k_4  [RC0402]  206.46 103.5 180 bottom
PR267  ev@100k/f_4  [RC0402]  197.8 102.15 180 bottom
PR269  ev@6.81k/f_4  [RC0402]  202.53 101.55 180 bottom
PR272  *ev@1/f_4  [RC0402]  200.85 99.36 90 bottom
PR273  *ev@499k/f_4  [RC0402]  201.92 99.34 270 bottom
PR274  ev@12.4k/f_4  [RC0402]  203.03 99.34 90 bottom
PR280  *gt3@0_4  [RC0402]  57.87 90.8 90 bottom
PR286  gt3@0_4  [RC0402]  55.84 86.61 270 bottom
PR287  gt3@0_4  [RC0402]  56.86 86.66 270 bottom
PR288  gt3@0_4  [RC0402]  57.87 86.66 90 bottom
PR289  gt3@100k/f_4  [RC0402]  58.89 86.61 90 bottom
PR290  gt3@0_4  [RC0402]  56.1 79.5 270 bottom
PR291  gt3@0_6  [RC0603]  59.27 79.24 90 bottom
PR292  gt3@0_4  [RC0402]  57.62 78.99 0 bottom
PR293  gt3@100k/f_4  [RC0402]  55.33 77.34 90 bottom
PR294  gt3@0_6  [RC0603]  57.62 76.7 90 bottom
PR295  100k/f_4  [RC0402]  175.3 69.9 0 bottom
PR296  200k/f_4  [RC0402]  175.3 68.78 180 bottom
PR297  10k/f_4  [RC0402]  183.35 68.42 180 bottom
PR298  *0_4  [RC0402]  173.44 68.32 90 bottom
PR299  100k/f_4  [RC0402]  175.3 67.69 180 bottom
PR300  30.1k/f_4  [RC0402]  183.86 66.8 90 bottom
PR301  *short_4  [SHORT0402]  174.03 66.54 0 bottom
PR302  *ev@0_4  [RC0402]  193.76 66.29 0 bottom
PR303  *0_4  [RC0402]  175.73 66.04 270 bottom
PR304  *ev@100k/f_4  [RC0402]  195.29 65.78 90 bottom
PR305  *short_4  [SHORT0402]  174.03 65.45 0 bottom
PR306  *ev@2.2_6  [RC0603]  188.05 65.27 0 bottom
PR307  *shortev@0_4  [SHORT0402]  194.27 64.77 270 bottom
PR308  2/f_6  [RC0603]  178.14 63.37 90 bottom
PR309  ev@10k/f_4  [RC0402]  193.26 62.73 270 bottom
PR310  ev@7.5k/f_4  [RC0402]  194.27 62.73 270 bottom
PR311  *shortev@0_4  [SHORT0402]  195.29 62.73 90 bottom
PR312  ev@10_6  [RC0603]  190.97 58.92 180 bottom
PR313  *4.7_6  [RC0603]  184.44 56.23 270 bottom
PR326  10k_4  [RC0402]  76.42 18.16 90 bottom
PR328  *short_4  [SHORT0402]  77.97 18.21 0 bottom
PR330  22.6k/f_4  [RC0402]  80.12 18.21 180 bottom
PR331  15k/f_4  [RC0402]  82.26 19.35 0 bottom
PR332  *short_4  [SHORT0402]  82.26 20.62 0 bottom
PR333  *short_4  [SHORT0402]  83.68 23.08 0 bottom
PR334  1m_6  [RC0603]  53.84 36.04 180 bottom
PR335  *1m_6  [RC0603]  53.84 34.64 180 bottom
PR336  1m_6  [RC0603]  53.94 32.1 180 bottom
PR337  1m_6  [RC0603]  53.94 30.83 0 bottom
PR338  22_8  [RC0805]  69.71 26.51 180 bottom
PR339  22_8  [RC0805]  57.95 27.78 0 bottom
PR340  100/f_4  [RC0402]  157.19 181.61 0 top
PR341  45.3/f_4  [RC0402]  157.19 182.88 0 top
PR342  31.6k/f_4  [RC0402]  210.02 195.96 180 top
PR343  *shortev@0_4  [SHORT0402]  196.2 104.8 270 top
PR344  gt3@10/f_4  [RC0402]  66.81 79.13 90 bottom
PR346  ev@200k/f_4  [RC0402]  210.4 117.09 90 bottom
PR6120  10k/f_4  [RC0402]  65.32 58.37 270 top
PR6121  10k/f_4  [RC0402]  66.33 58.37 270 top
PR6122  100k/f_4  [RC0402]  67.48 57.6 90 top
PR6124  120k/f_4  [RC0402]  64.19 57.57 270 top
PR6125  *short_6  [SHORT0603]  68.62 56.59 90 top
PR6130  *short_6  [SHORT0603]  67.65 50.32 0 top
PR6275  22_8  [RC0805]  61.51 61.16 0 bottom
PR6278  *short_4  [SHORT0402]  64.12 59.01 0 bottom
PR6279  6.49k/f_4  [RC0402]  67.04 58.47 90 bottom
PR6280  10k/f_4  [RC0402]  65.8 58.47 270 bottom
PR6281  15.8k/f_4  [RC0402]  64.12 57.98 0 bottom
PR6283  *short_4  [SHORT0402]  69.51 55.66 0 bottom
PR6284  *100k/f_4  [RC0402]  70.4 54.63 0 bottom
PR6285  *short_6  [SHORT0603]  60.91 54.44 0 bottom
PR6286  1/f_6  [RC0603]  70.67 52.12 180 bottom
PR6287  1/f_6  [RC0603]  60.93 51.82 180 bottom
PR6288  *4.7_6  [RC0603]  67.12 44.3 270 bottom
PR6289  *4.7_6  [RC0603]  71.05 44.2 270 bottom
PR6290  *10k/f_4  [RC0402]  88.46 32.23 270 top
PU1  isl95859hrtz-t  [QFN40-5X5-4-41P-ISL62771HRTZ-T]  149.83 181.68 180 top
PU3  ev@up1658rqkf  [QFN20-3X3-4-21P-0_8H]  202.35 103.32 270 top
PU4  as393mtr-e1  [SOIC8-6-1_27]  70.45 68.7 180 top
PU5  bq24780sruyr  [QFN28-4X4-4-38P]  205.45 195.74 0 bottom
PU6  aoz5029qi-5  [POWER-3_5X5-5-14P]  125.69 166.49 0 bottom
PU7  aoz5029qi-5  [POWER-3_5X5-5-14P]  134.96 165.22 0 bottom
PU8  aoz5029qi-5  [POWER-3_5X5-5-14P]  145.88 165.1 0 bottom
PU9  aoz5029qi-5  [POWER-3_5X5-5-14P]  156.68 165.1 0 bottom
PU10  apw8824  [TSOP6-2_8-95]  103.85 137.28 270 bottom
PU11  ev@nb671gq-z  [QFN14-3X3-4-16P]  215.1 119.12 180 bottom
PU12  rt8237czqw  [SON10-3X3-5-16P]  75.96 112.77 90 bottom
PU14  gt3@nb681gd-z  [QFN13-2X3-5]  57.62 82.93 90 bottom
PU15  g5316rz1d  [QFN20-3X3-4-26P]  179.34 67.64 0 bottom
PU16  ev@rt8068azqw  [DFN10-3X3-5-11P-RT9296]  190.97 63.75 0 bottom
PU19  apw8824  [TSOP6-2_8-95]  79.08 20.62 180 bottom
PU6010  tps51225rukr  [QFN20-3X3-4-26P]  65.77 53.92 0 bottom
Q1  *tsi@2n7002k  [SOT23_213-3_3-2]  147.66 197.99 180 top
Q2  *tsi@2n7002dw  [SC70-2_1-65-6P]  141.31 192.91 180 top
Q3  2n7002dw  [SC70-2_1-65-6P]  112.23 175.89 90 top
Q4  dtc144eua  [UMT_213-3-1_3]  115.28 174.06 270 top
Q5  mmbt3904-7-f  [SOT23_213-3_3-2]  163.28 158.49 90 top
Q6  ev@dtc144eu  [UMT_213-3-1_3]  161.51 149.55 0 top
Q7  ev@metr3904-g  [SOT23_213-3_3-2]  168.11 146.2 180 top
Q8  ev@mmbt3904-7-f  [SOT23_213-3_3-2]  164.05 144.52 270 top
Q9  ev@2n7002k  [SOT23_213-3_3-2]  191.87 144.18 0 top
Q10  ev@2n7002k  [SOT23_213-3_3-2]  174.33 143.63 0 top
Q11  gt@ao3413  [SOT23_213-3_3-2]  207.99 143.25 270 top
Q12  ev@dtc144eua  [UMT_213-3-1_3]  168.24 142.87 0 top
Q13  ev@2n7002dw  [SC70-2_1-65-6P]  202.67 141.26 180 top
Q14  *2n7002k  [SOT23_213-3_3-2]  175.73 139.7 180 top
Q15  *2n7002k  [SOT23_213-3_3-2]  171.92 139.57 270 top
Q16  ev@2n7002k  [SOT23_213-3_3-2]  197.29 135.63 90 top
Q17  gt@2n7002k  [SOT23_213-3_3-2]  209.23 134.49 270 top
Q18  kbl@ao3413  [SOT23_213-3_3-2]  212.94 134.49 270 top
Q19  kbl@dtc144eu  [UMT_213-3-1_3]  209.89 130.55 270 top
Q20  tdi@2n7002k  [SOT23_213-3_3-2]  177.05 121.56 0 top
Q21  ap2331sa-7  [SOT23_213-3_3-2]  13.04 112.77 180 top
Q22  ioac@ao3413  [SOT23_213-3_3-2]  181.7 104.77 270 top
Q23  2n7002dw  [SC70-2_1-65-6P]  186.27 96.64 90 top
Q24  ioac@ao3413  [SOT23_213-3_3-2]  46.95 92.07 270 top
Q25  2n7002k  [SOT23_213-3_3-2]  40.47 80.51 90 top
Q26  ap2331sa-7  [SOT23_213-3_3-2]  17.61 74.93 180 top
Q27  *dtc144eu  [UMT_213-3-1_3]  30.82 50.8 270 top
Q28  *ao3404  [SOT23_213-3_3-2]  34.25 50.67 270 top
Q29  *pja138k  [SOT23_213-3_3-2]  42.76 43.94 90 top
Q30  2n7002k  [SOT23_213-3_3-2]  206.46 33.27 90 top
Q31  fdv301n  [SOT23_213-3_3-2]  163.28 158.49 90 bottom
Q32  2n7002dw  [SC70-2_1-65-6P]  165.21 126.95 180 bottom
Q34  ioac@ao6402a  [TSOP6-2_8-95]  219.21 97.91 180 bottom
Q35  *dtc144eu  [UMT_213-3-1_3]  101.69 97.15 90 bottom
Q36  ioac@dmn601k-7  [SOT23_213-3_3-2]  223.23 94.23 180 bottom
Q37  ioac@2n7002dw  [SC70-2_1-65-6P]  218.91 92.32 0 bottom
Q38  *ioac@ao3413  [SOT23_213-3_3-2]  174.56 89.25 270 bottom
Q39  ioac@2n7002k  [SOT23_213-3_3-2]  46.09 87.12 90 bottom
Q40  pja138k  [SOT23_213-3_3-2]  208.62 75.69 0 bottom
Q41  2n7002k  [SOT23_213-3_3-2]  17.11 75.05 270 bottom
Q42  *ao3413  [SOT23_213-3_3-2]  205.93 25.85 180 bottom
Q43  tdi@2n7002dw  [SC70-2_1-65-6P]  200.75 23.11 180 bottom
Q56  *pj4n3kdw  [SC70-2_1-65-6P]  215.73 74.93 0 bottom
R1  *short_4  [SHORT0402]  133.95 198.5 0 top
R2  *short_4  [SHORT0402]  133.95 197.48 0 top
R3  tsu@0_4  [RC0402]  140.55 198.12 90 top
R4  tsu@0_4  [RC0402]  141.69 198.12 90 top
R5  *tsi@0_4  [RC0402]  140.55 197.33 270 top
R6  *tsi@0_4  [RC0402]  141.69 197.33 270 top
R7  *tsi@10k_4  [RC0402]  145.12 196.59 270 top
R8  *tsi@0_4  [RC0402]  145.5 194.94 0 top
R9  *tsi@10k_4  [RC0402]  142.33 194.81 180 top
R10  *tsi@0_4  [RC0402]  140.27 194.56 180 top
R11  *short_6  [SHORT0603]  129.12 192.4 180 top
R12  *tsi@10k_4  [RC0402]  140.3 191 0 top
R13  *tsi@0_4  [RC0402]  142.33 191 180 top
R14  *short_8  [SHORT0805]  124.17 190.11 90 top
R15  *short_8  [SHORT0805]  126.2 190.11 90 top
R16  *short_6  [SHORT0603]  134.45 189.48 0 top
R17  ev@100/f_4  [RC0402]  193.64 188.97 0 top
R18  ev@100/f_4  [RC0402]  195.8 188.97 180 top
R19  *0_4  [RC0402]  132.55 188.34 180 top
R20  ev@100/f_4  [RC0402]  193.64 187.83 0 top
R21  ev@100/f_4  [RC0402]  195.8 187.83 180 top
R22  ev@100/f_4  [RC0402]  201 187.7 0 top
R23  ev@100/f_4  [RC0402]  203.16 187.7 180 top
R24  ev@100/f_4  [RC0402]  201 186.56 0 top
R25  ev@100/f_4  [RC0402]  203.16 186.56 180 top
R26  ev@100/f_4  [RC0402]  193.64 186.3 0 top
R27  ev@100/f_4  [RC0402]  195.8 186.3 180 top
R28  *short_8  [SHORT0805]  131.03 185.54 180 top
R29  ev@100/f_4  [RC0402]  193.64 185.16 0 top
R30  ev@100/f_4  [RC0402]  195.8 185.16 180 top
R31  ev@100/f_4  [RC0402]  201 185.16 0 top
R32  ev@100/f_4  [RC0402]  203.16 185.16 180 top
R33  ev@1.33k/f_4  [RC0402]  165.8 184.27 270 top
R34  ev@1.33k/f_4  [RC0402]  168.11 184.27 90 top
R35  ev@100/f_4  [RC0402]  201 184.02 0 top
R36  ev@100/f_4  [RC0402]  203.16 184.02 180 top
R37  *short_4  [SHORT0402]  114.01 183.89 270 top
R38  100k_4  [RC0402]  115.02 183.89 270 top
R39  ev@100/f_4  [RC0402]  193.64 183.64 0 top
R40  ev@100/f_4  [RC0402]  195.67 183 270 top
R41  ev@100/f_4  [RC0402]  201 182.67 0 top
R42  ev@100/f_4  [RC0402]  203.16 182.67 180 top
R43  ev@10k/f_4  [RC0402]  193.64 182.52 0 top
R44  dr@243_4  [RC0402]  168.11 182.22 90 top
R45  ev@100/f_4  [RC0402]  201 181.61 0 top
R46  ev@100/f_4  [RC0402]  203.16 181.61 180 top
R47  ev@10k/f_4  [RC0402]  193.64 181.38 180 top
R48  ev@100/f_4  [RC0402]  193.64 180.21 0 top
R49  ev@100/f_4  [RC0402]  195.8 180.21 180 top
R50  ev@100/f_4  [RC0402]  201 180.21 0 top
R51  ev@100/f_4  [RC0402]  203.16 180.21 180 top
R52  10k_4  [RC0402]  112.1 179.57 270 top
R53  *100k_4  [RC0402]  113.25 179.57 90 top
R54  ev@100/f_4  [RC0402]  193.76 179.07 180 top
R55  ev@100/f_4  [RC0402]  201 179.07 0 top
R56  ev@100/f_4  [RC0402]  203.16 179.07 180 top
R57  ev@100/f_4  [RC0402]  193.89 177.92 0 top
R58  10k_4  [RC0402]  116.17 177.41 270 top
R59  ev@10k/f_4  [RC0402]  200.49 177.41 270 top
R60  ev@10k/f_4  [RC0402]  201.64 177.41 90 top
R61  ev@100/f_4  [RC0402]  193.89 176.78 0 top
R62  ev@100/f_4  [RC0402]  196.05 176.78 180 top
R63  ev@100/f_4  [RC0402]  193.89 175.64 0 top
R64  ev@100/f_4  [RC0402]  196.05 175.64 180 top
R65  100k_4  [RC0402]  111.09 172.87 270 top
R66  *short_4  [SHORT0402]  112.1 172.59 90 top
R67  *short_4  [SHORT0402]  113.12 172.59 90 top
R68  ev@162_4  [RC0402]  181.19 172.33 0 top
R69  dr@243_4  [RC0402]  182.84 171.83 90 top
R70  dr@243_4  [RC0402]  197.07 167.51 270 top
R71  ev@51.1/f_4  [RC0402]  192.6 165.53 270 top
R72  ev@0_6  [RC0603]  167.37 164.05 90 top
R73  ev@42.2/f_4  [RC0402]  193.13 163.95 0 top
R74  1k_4  [RC0402]  163.82 161.67 90 top
R75  ev@162_4  [RC0402]  208.75 157.48 0 top
R76  ev@1.33k/f_4  [RC0402]  219.04 157.09 0 top
R77  ev@1.33k/f_4  [RC0402]  207.1 156.71 270 top
R78  dr@243_4  [RC0402]  208.75 156.33 0 top
R79  ev@10k/f_4  [RC0402]  170.59 153.73 180 top
R80  *60.4_4  [RC0402]  195.67 150.11 0 top
R81  ev@4.7k_4  [RC0402]  163.92 149.09 270 top
R82  ev@4.7k_4  [RC0402]  169.53 149.02 270 top
R83  ev@4.7k_4  [RC0402]  165.06 148.97 90 top
R84  ev@40.2/f_4  [RC0402]  195.67 148.97 0 top
R85  1k_4  [RC0402]  157.7 148.84 0 top
R86  ev@0_4  [RC0402]  167.68 148.59 0 top
R87  *60.4_4  [RC0402]  195.67 147.82 0 top
R88  *100k/f_4  [RC0402]  161.12 147.49 0 top
R89  60.4/f_4  [RC0402]  159.6 147.04 90 top
R90  ev@1.5k/f_4  [RC0402]  161.12 146.48 180 top
R91  ev@10k/f_4  [RC0402]  174.97 146.05 0 top
R92  *0_4  [RC0402]  171.79 144.01 90 top
R93  *10k/f_4  [RC0402]  196.56 143.4 90 top
R94  ev@10k/f_4  [RC0402]  194.36 143.39 90 top
R95  ev@10k/f_4  [RC0402]  195.52 143.38 90 top
R96  100/f_4  [RC0402]  146.65 144.14 180 top
R97  gm@0_8  [RC0805]  210.91 143.12 90 top
R98  100/f_4  [RC0402]  146.01 143.12 0 top
R99  *10k/f_4  [RC0402]  171.28 142.24 180 top
R100  ev@2.2k_4  [RC0402]  199.73 141.35 270 top
R101  ev@2.2k_4  [RC0402]  205.45 141.22 90 top
R102  0_4  [RC0402]  195.06 88.26 270 top
R103  *0_4  [RC0402]  194.02 88.26 270 top
R104  ev@4.7k_4  [RC0402]  164.3 140.97 180 top
R105  ev@100k/f_4  [RC0402]  166.48 140.33 90 top
R106  gt@0_4  [RC0402]  168.52 140.28 90 top
R107  gt@0_4  [RC0402]  169.53 140.28 270 top
R108  ev@4.7k_4  [RC0402]  167.5 140.28 270 top
R109  100/f_4  [RC0402]  151.47 140.2 0 top
R110  *10k_4  [RC0402]  168.62 138.76 180 top
R111  ev@100k/f_4  [RC0402]  197.32 138.68 180 top
R112  *short_6  [SHORT0603]  149.69 136.65 270 bottom
R113  *0_4  [RC0402]  160.36 138.2 0 top
R114  ev@100k/f_4  [RC0402]  191.94 138.15 90 top
R115  iv@1k_4  [RC0402]  168.62 137.71 180 top
R116  gt@100k_4  [RC0402]  207.99 137.54 270 top
R117  gt@10k_4  [RC0402]  209.13 137.54 90 top
R118  ev@10k_4  [RC0402]  210.27 137.54 90 top
R119  *shortkbl@0_4  [SHORT0402]  211.42 137.54 90 top
R120  ev@0_4  [RC0402]  174.94 137.28 180 top
R121  ev@10k/f_4  [RC0402]  176.97 137.28 0 top
R122  100/f_4  [RC0402]  153.5 139.95 0 top
R123  ev@100_4  [RC0402]  185.76 136.93 180 top
R124  ev@100_4  [RC0402]  190.08 136.77 180 top
R125  *0_4  [RC0402]  170.78 137.16 180 top
R126  ev@100k/f_4  [RC0402]  172.94 136.7 90 top
R127  ev@100k_4  [RC0402]  167.22 136.27 0 top
R128  ev@0_4  [RC0402]  174.94 136.27 0 top
R129  *0_4  [RC0402]  176.97 136.27 180 top
R130  *10k_4  [RC0402]  162.29 136.14 270 top
R131  *0_4  [RC0402]  163.31 136.14 270 top
R132  gm@0_4  [RC0402]  191.94 136.11 90 top
R134  54.9/f_4  [RC0402]  112.74 138.68 270 bottom
R135  *short_6  [SHORT0603]  151.85 134.62 270 top
R137  gm@0_4  [RC0402]  171.06 135.96 0 top
R138  100/f_4  [RC0402]  111.47 138.68 270 bottom
R139  gt@0_4  [RC0402]  176.49 134.23 90 top
R140  *0_4  [RC0402]  177.51 134.23 90 top
R142  gt@100k/f_4  [RC0402]  193.71 134.08 270 top
R143  ev@0_4  [RC0402]  192.11 133.98 270 top
R145  100/f_4  [RC0402]  153.12 129.66 270 top
R148  kbl@10k_4  [RC0402]  212.69 131.82 0 top
R152  2.2k_4  [RC0402]  163.79 128.27 180 top
R153  1.5k/f_4  [RC0402]  156.15 128.49 180 top
R154  24.9/f_4  [RC0402]  134.58 127.88 180 top
R155  100/f_4  [RC0402]  111.59 130.68 0 top
R156  49.9/f_4  [RC0402]  114.26 130.68 270 top
R158  49.9/f_4  [RC0402]  111.72 126.61 180 top
R160  *10k_4  [RC0402]  156.45 126.13 180 top
R161  100/f_4  [RC0402]  109.31 130.68 0 top
R162  49.9/f_4  [RC0402]  111.72 127.88 180 top
R164  *0_4  [RC0402]  176.49 123.92 0 top
R165  *2.2k_4  [RC0402]  156.43 123.82 270 top
R166  2.2k_4  [RC0402]  158.46 123.57 90 top
R167  2.2k_4  [RC0402]  159.55 123.57 90 top
R169  *2.2k_4  [RC0402]  157.44 123.57 270 top
R171  *short_4  [SHORT0402]  166.18 122.83 0 top
R172  gt3@100/f_4  [RC0402]  85.69 104.39 0 top
R174  200/f_4  [RC0402]  158.33 122.04 0 top
R175  *short_4  [SHORT0402]  166.18 121.81 180 top
R176  gt3@100/f_4  [RC0402]  85.69 103.37 0 top
R177  tdi@100k_4  [RC0402]  179.44 117.55 90 top
R178  113/f_4  [RC0402]  158.33 121.03 180 top
R179  *short_6  [SHORT0603]  168.49 121.03 180 top
R180  *short_6  [SHORT0603]  162.24 118.84 90 top
R182  *short_6  [SHORT0603]  161.2 120.72 180 top
R185  *short_6  [SHORT0603]  168.8 118.36 270 top
R186  *short_6  [SHORT0603]  178.27 118.23 90 top
R187  *short_6  [SHORT0603]  161.1 118.49 270 top
R188  *short_6  [SHORT0603]  166.89 116.89 180 top
R190  33_4  [RC0402]  209.13 17.52 270 top
R192  *short_6  [SHORT0603]  164.81 117.92 270 top
R193  *short_6  [SHORT0603]  166.79 115.69 180 top
R194  *short_4  [SHORT0402]  132.37 115.57 90 top
R195  *1k_4  [RC0402]  166.38 114.6 0 top
R196  *iv@10k_4  [RC0402]  162.09 114.52 270 top
R198  *short_6  [SHORT0603]  168.72 114.19 0 top
R199  *10k_4  [RC0402]  163.66 114.02 90 top
R200  *2.2k_4  [RC0402]  21.55 113.79 90 top
R201  *2.2k_4  [RC0402]  22.57 113.79 90 top
R202  *10k_4  [RC0402]  24.6 113.79 90 top
R203  *0_6  [RC0603]  19.65 113.41 0 top
R204  *10k_4  [RC0402]  172.43 114.42 180 top
R205  *150k_4  [RC0402]  176.62 112.01 270 top
R206  200/f_4  [RC0402]  16.88 111.37 90 top
R207  *1k_4  [RC0402]  166.2 111.88 0 top
R208  10k_4  [RC0402]  175.48 112.01 90 top
R209  10k_4  [RC0402]  227.8 110.99 0 top
R210  *0_6  [RC0603]  172.99 110.66 180 top
R211  10k_4  [RC0402]  165.44 110.23 0 top
R212  *short_6  [SHORT0603]  171.03 109.88 90 top
R213  75/f_4  [RC0402]  16.29 109.17 270 top
R214  100k_4  [RC0402]  174.03 107.97 90 top
R215  10k_4  [RC0402]  167.58 108.53 180 top
R216  10k_4  [RC0402]  228.31 108.33 270 top
R217  33_4  [RC0402]  228.05 106.68 180 top
R218  *10k_4  [RC0402]  55.59 107.69 0 top
R219  75/f_4  [RC0402]  16.29 107.13 90 top
R220  *ev@10k_4  [RC0402]  175.09 105.53 90 top
R221  ioac@0_8  [RC0805]  184.62 105.53 90 top
R222  75/f_4  [RC0402]  16.29 105.1 90 top
R223  10k_4  [RC0402]  171.54 104.26 0 top
R224  *short_4  [SHORT0402]  173.57 104.39 180 top
R225  22/j_4  [RC0402]  19.95 103.4 270 top
R226  22/j_4  [RC0402]  21.17 103.37 270 top
R227  10k_4  [RC0402]  169.51 102.87 180 top
R228  10k_4  [RC0402]  171.54 102.87 180 top
R229  *short_4  [SHORT0402]  169.51 101.85 180 top
R230  ioac@10k_4  [RC0402]  180.05 100.99 0 top
R231  *ioac@100k/j_4  [RC0402]  182.08 100.96 0 top
R232  *1k_4  [RC0402]  174.84 100.83 270 top
R234  10k_4  [RC0402]  169 100.33 90 top
R235  *short_4  [SHORT0402]  170.01 100.33 90 top
R237  nac@0_8  [RC0805]  188.3 99.94 180 top
R238  *4m@33_4  [RC0402]  174.84 98.8 270 top
R239  8m4m@15_4  [RC0402]  173.32 98.04 0 top
R240  *short_6  [SHORT0603]  170.8 97.96 270 top
R241  *10k_4  [RC0402]  184.37 97.91 270 top
R242  4.7k/j_4  [RC0402]  183.35 95.63 90 top
R243  *0/j_4  [RC0402]  184.37 95.63 270 top
R244  *0_4  [RC0402]  183.98 93.98 180 top
R245  4.7k/j_4  [RC0402]  187.41 94.1 180 top
R246  *short_8  [SHORT0805]  39.97 93.47 270 top
R247  nac@0_8  [RC0805]  42 93.47 270 top
R248  ioac@0_8  [RC0805]  44.03 93.47 90 top
R249  1m_4  [RC0402]  163.79 93.09 90 top
R250  10k_4  [RC0402]  165.32 93.09 90 top
R251  75/f_6  [RC0603]  18.25 92.96 0 top
R252  *short_6  [SHORT0603]  161.51 92.71 90 top
R253  *0/j_4  [RC0402]  185 92.71 180 top
R254  0_4  [RC0402]  207.86 92.45 90 top
R255  10m_4  [RC0402]  156.93 92.07 90 top
R256  *100k_4  [RC0402]  165.19 91.05 0 top
